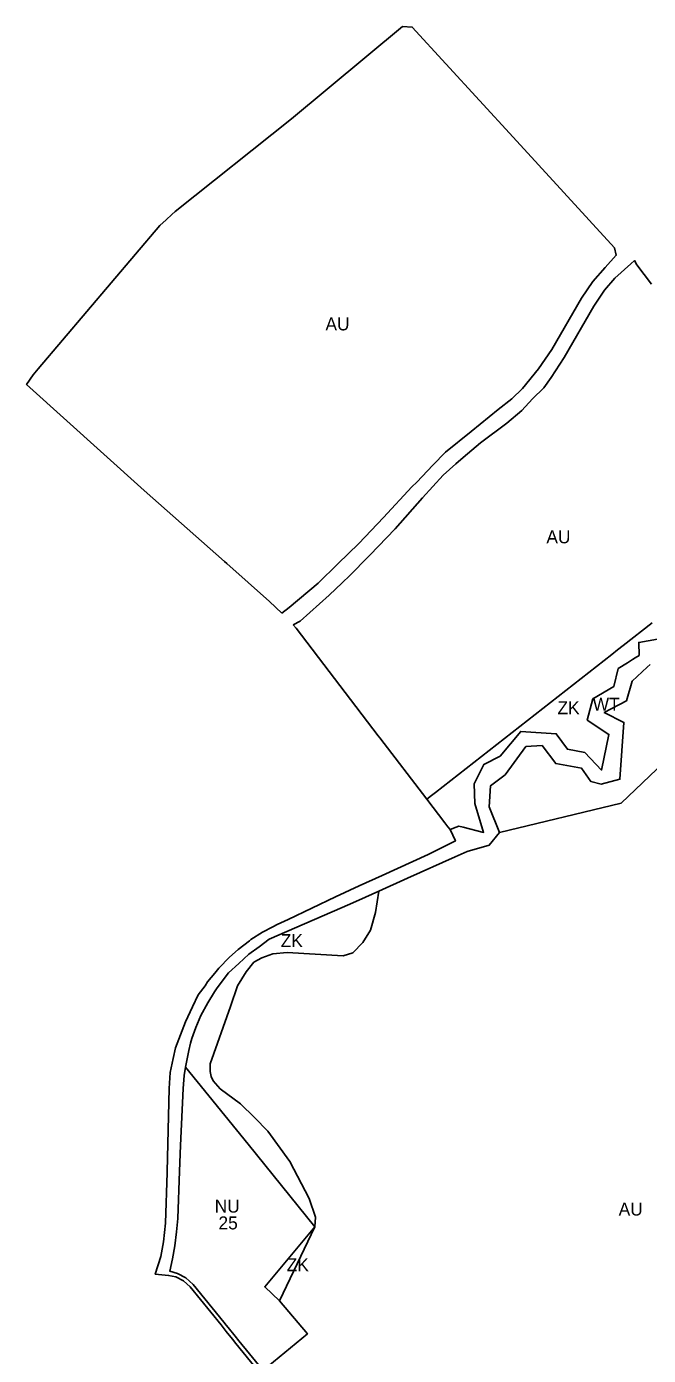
# Model space of a CAD drawing. Extents: x -522079 to -518833, y -1142398 to -1139961.
# Drawn here: x -522079 to -521599, y -1141061 to -1140036 of the extents above; entities that cross this region are included whole.
import ezdxf

# ---------------------------------------------------------------- set-up
doc = ezdxf.new("R2010")
doc.units = 0
for name, color, linetype in [('90640013', 7, 'Continuous'), ('90710013', 7, 'Continuous'), ('90730023', 7, 'Continuous'), ('90750013', 7, 'Continuous'), ('ID_navrh', 7, 'Continuous')]:
    doc.layers.add(name, color=color, linetype=linetype)

msp = doc.modelspace()

# ---------------------------------------------------------------- linework, layer by layer
at = {"layer": '90640013'}
for points in [[(-521592.51, -1140508.64), (-521606.9, -1140511.13), (-521606.6, -1140521.1), (-521609.78, -1140523.1), (-521611.69, -1140524.3), (-521615.57, -1140526.74), (-521622.75, -1140531.26), (-521626.2, -1140545.21), (-521642.26, -1140554.66), (-521646.65, -1140571), (-521629.87, -1140582.04), (-521635.54, -1140609.6), (-521648.43, -1140596.09), (-521661.89, -1140593.5), (-521670.5, -1140581.53), (-521698, -1140579.74), (-521713.89, -1140598.84), (-521726.52, -1140605.2), (-521734.01, -1140620.28), (-521733.38, -1140635.33), (-521726.67, -1140657.74), (-521742.5, -1140653.65), (-521745.77, -1140652.8), (-521747.72, -1140653.54), (-521752.49, -1140655.36), (-521748.38, -1140664.24), (-521769.34, -1140674.65), (-521804.78, -1140690.88), (-521822.52, -1140699.01), (-521840.82, -1140707.39), (-521877.29, -1140724.81), (-521885.86, -1140728.85), (-521889.34, -1140730.49), (-521897.11, -1140734.61), (-521906.16, -1140740.38), (-521907.36, -1140741.3), (-521915.99, -1140747.92), (-521922.69, -1140753.87), (-521930.99, -1140762.54), (-521933.99, -1140766.2), (-521939.58, -1140773.02), (-521941.53, -1140776.07), (-521946.81, -1140782.96), (-521951.34, -1140792.2), (-521956.64, -1140803.89), (-521960.5, -1140813.97), (-521964.35, -1140823.92), (-521966.23, -1140832.06), (-521968.4, -1140842.82), (-521969.35, -1140855.23), (-521970.78, -1140919.37), (-521970.73, -1140920.13), (-521972.01, -1140959.19), (-521973.56, -1140973.69), (-521975.77, -1140984.83), (-521980.02, -1140998.54), (-521969.71, -1140999.55), (-521964.16, -1141000.63), (-521958.05, -1141003.66), (-521952.92, -1141008.37), (-521929.14, -1141037.67), (-521925.3, -1141042.86), (-521920.31, -1141048.71), (-521917.71, -1141051.91), (-521886.17, -1141090.77)], [(-521896.82, -1141072.9), (-521915.45, -1141049.99), (-521918.24, -1141046.46), (-521923.77, -1141039.61), (-521925.13, -1141037.95), (-521927.04, -1141035.61), (-521950.59, -1141006.47), (-521956.25, -1141001.25), (-521962.85, -1140997.93), (-521968.74, -1140996.16), (-521966.75, -1140986.81), (-521964.79, -1140976.78), (-521963.61, -1140965.78), (-521962.64, -1140955.52), (-521961.27, -1140919.13), (-521960.41, -1140899.15), (-521958.48, -1140855.25), (-521957.55, -1140845.37), (-521956.51, -1140838.94), (-521956.06, -1140836.18), (-521953.99, -1140825.94), (-521952.78, -1140820.25), (-521951.85, -1140816.81), (-521948.6, -1140808.27), (-521944.68, -1140798.86), (-521939.28, -1140789.17), (-521934.35, -1140780.63), (-521932.78, -1140778.46), (-521929.14, -1140773.45), (-521923.36, -1140766.09), (-521915.35, -1140758.73), (-521907.65, -1140751.59), (-521899.73, -1140746), (-521892.09, -1140739.95), (-521829.78, -1140713), (-521817.76, -1140707.64), (-521807.36, -1140702.96), (-521785.36, -1140693.05), (-521748.53, -1140676.5), (-521739.27, -1140672.34), (-521722.24, -1140667.6), (-521714.47, -1140657.84), (-521722.39, -1140637.91), (-521721.28, -1140621.72), (-521710.1, -1140613.29), (-521693.94, -1140591.41), (-521681.44, -1140590.68), (-521670.89, -1140604.59), (-521650.96, -1140608.19), (-521643.99, -1140618.34), (-521635.78, -1140620.38), (-521621.47, -1140616.67), (-521618.3, -1140572.85), (-521633.5, -1140565.29), (-521616.47, -1140556.14), (-521611.96, -1140540.86), (-521600.31, -1140530.11), (-521598.04, -1140528.01)]]:
    msp.add_lwpolyline(points, dxfattribs=at)
at = {"layer": '90710013'}
for points in [[(-521596.59, -1140495.96), (-521619, -1140513.52), (-521623.29, -1140516.88), (-521627.73, -1140520.35), (-521763.73, -1140626.86), (-521766.84, -1140629.25), (-521770.53, -1140631.96)], [(-521770.53, -1140631.96), (-521756.45, -1140650.36), (-521754.23, -1140653.26), (-521752.49, -1140655.36), (-521747.72, -1140653.54), (-521745.77, -1140652.8), (-521742.5, -1140653.65), (-521726.67, -1140657.74), (-521733.38, -1140635.33), (-521734.01, -1140620.28), (-521726.52, -1140605.2), (-521713.89, -1140598.84), (-521698, -1140579.74), (-521670.5, -1140581.53), (-521661.89, -1140593.5), (-521648.43, -1140596.09), (-521635.54, -1140609.6), (-521629.87, -1140582.04), (-521646.65, -1140571), (-521642.26, -1140554.66), (-521626.2, -1140545.21), (-521622.75, -1140531.26), (-521615.57, -1140526.74), (-521611.69, -1140524.3), (-521609.78, -1140523.1), (-521606.6, -1140521.1), (-521606.9, -1140511.13), (-521592.51, -1140508.64)], [(-521598.04, -1140528.01), (-521600.31, -1140530.11), (-521611.96, -1140540.86), (-521616.47, -1140556.14), (-521633.5, -1140565.29), (-521618.3, -1140572.85), (-521621.47, -1140616.67), (-521635.78, -1140620.38), (-521643.99, -1140618.34), (-521650.96, -1140608.19), (-521670.89, -1140604.59), (-521681.44, -1140590.68), (-521693.94, -1140591.41), (-521710.1, -1140613.29), (-521721.28, -1140621.72), (-521722.39, -1140637.91), (-521714.47, -1140657.84), (-521620.49, -1140635.2), (-521571.05, -1140588.16)], [(-521956.51, -1140838.94), (-521908.14, -1140898.33), (-521856.78, -1140962.03), (-521856.34, -1140954.66), (-521861.19, -1140940.1), (-521876.05, -1140911.7), (-521892.98, -1140888.32), (-521903.5, -1140877.67), (-521914.17, -1140867.15), (-521929.85, -1140855.48), (-521935.25, -1140849.47), (-521936.78, -1140845.99), (-521937.7, -1140842.11), (-521937.7, -1140836.22), (-521922.02, -1140791.92), (-521916.45, -1140776.17), (-521909.81, -1140765.14), (-521903.79, -1140757.88), (-521897.69, -1140754.5), (-521889.21, -1140751.5), (-521878.09, -1140750.44), (-521834.89, -1140752.79), (-521827.42, -1140750.62), (-521819.79, -1140742.52), (-521813.81, -1140733.11), (-521809.93, -1140719.56), (-521807.36, -1140702.96), (-521817.76, -1140707.64), (-521829.78, -1140713), (-521892.09, -1140739.95), (-521899.73, -1140746), (-521907.65, -1140751.59), (-521915.35, -1140758.73), (-521923.36, -1140766.09), (-521929.14, -1140773.45), (-521932.78, -1140778.46), (-521934.35, -1140780.63), (-521939.28, -1140789.17), (-521944.68, -1140798.86), (-521948.6, -1140808.27), (-521951.85, -1140816.81), (-521952.78, -1140820.25), (-521953.99, -1140825.94), (-521956.06, -1140836.18), (-521956.51, -1140838.94)]]:
    msp.add_lwpolyline(points, dxfattribs=at)
msp.add_lwpolyline([(-521884.07, -1141019.15), (-521856.78, -1140962.03), (-521895.5, -1141008.4)], close=True, dxfattribs=at)
at = {"layer": '90730023'}
msp.add_lwpolyline([(-521893.06, -1141069.8), (-521862.5, -1141044.56), (-521884.07, -1141019.15), (-521895.5, -1141008.4), (-521856.78, -1140962.03), (-521908.14, -1140898.33), (-521956.51, -1140838.94), (-521957.55, -1140845.37), (-521958.48, -1140855.25), (-521960.41, -1140899.15), (-521961.27, -1140919.13), (-521962.64, -1140955.52), (-521963.61, -1140965.78), (-521964.79, -1140976.78), (-521966.75, -1140986.81), (-521968.74, -1140996.16), (-521962.85, -1140997.93), (-521956.25, -1141001.25), (-521950.59, -1141006.47), (-521927.04, -1141035.61), (-521925.13, -1141037.95), (-521923.77, -1141039.61), (-521918.24, -1141046.46), (-521915.45, -1141049.99), (-521896.82, -1141072.9)], dxfattribs=at)
at = {"layer": '90750013'}
msp.add_lwpolyline([(-521882.18, -1140488.56), (-521876.66, -1140484.09), (-521854.3, -1140465.27), (-521839, -1140450.48), (-521822.79, -1140434.86), (-521803.88, -1140414.74), (-521781.95, -1140390.97), (-521778.1, -1140387.34), (-521765.79, -1140374.26), (-521755.99, -1140364.38), (-521736.25, -1140348.4), (-521715.5, -1140331.4), (-521704.79, -1140323.18), (-521696.71, -1140315.1), (-521684.15, -1140299.89), (-521673.96, -1140285.19), (-521651.12, -1140245.38), (-521642.31, -1140232.52), (-521632.85, -1140221.77), (-521624.31, -1140212.38), (-521625.65, -1140206.61), (-521703.78, -1140121.15), (-521781.62, -1140036.36), (-521789.25, -1140035.92), (-521874.73, -1140107.13), (-521964.54, -1140178.59), (-521967.11, -1140180.95), (-521971.46, -1140184.95), (-521976.31, -1140189.41), (-522070.23, -1140300.06), (-522074.19, -1140304.73), (-522079.24, -1140312.2), (-521988.52, -1140393.86), (-521926.43, -1140448.75), (-521924.65, -1140450.32), (-521891.73, -1140479.43)], close=True, dxfattribs=at)
for points in [[(-521596.95, -1140234.61), (-521608.33, -1140219.87), (-521610.22, -1140216.5), (-521613.09, -1140218.9), (-521625.36, -1140230.13), (-521633.25, -1140239.25), (-521641.46, -1140251.62), (-521664.44, -1140291.34), (-521674.58, -1140306.67), (-521680.22, -1140314.66), (-521688.85, -1140323.27), (-521697.12, -1140332.11), (-521708.67, -1140341.98), (-521728.93, -1140357.06), (-521742.3, -1140368.5), (-521747.91, -1140373.33), (-521757.78, -1140381.98), (-521773.82, -1140399.6), (-521794.87, -1140423.48), (-521814.39, -1140443.83), (-521815.4, -1140444.86), (-521829.77, -1140459.58), (-521835.62, -1140465.09), (-521845.84, -1140474.71), (-521868.24, -1140494.75), (-521873.47, -1140497.6)], [(-521873.47, -1140497.6), (-521871.3, -1140500.06), (-521807.95, -1140583.04), (-521806.71, -1140584.66), (-521770.53, -1140631.96), (-521766.84, -1140629.25), (-521763.73, -1140626.86), (-521627.73, -1140520.35), (-521623.29, -1140516.88), (-521619, -1140513.52), (-521596.59, -1140495.96)], [(-521571.05, -1140588.16), (-521620.49, -1140635.2), (-521714.47, -1140657.84), (-521722.24, -1140667.6), (-521739.27, -1140672.34), (-521748.53, -1140676.5), (-521785.36, -1140693.05), (-521807.36, -1140702.96), (-521809.93, -1140719.56), (-521813.81, -1140733.11), (-521819.79, -1140742.52), (-521827.42, -1140750.62), (-521834.89, -1140752.79), (-521878.09, -1140750.44), (-521889.21, -1140751.5), (-521897.69, -1140754.5), (-521903.79, -1140757.88), (-521909.81, -1140765.14), (-521916.45, -1140776.17), (-521922.02, -1140791.92), (-521937.7, -1140836.22), (-521937.7, -1140842.11), (-521936.78, -1140845.99), (-521935.25, -1140849.47), (-521929.85, -1140855.48), (-521914.17, -1140867.15), (-521903.5, -1140877.67), (-521892.98, -1140888.32), (-521876.05, -1140911.7), (-521861.19, -1140940.1), (-521856.34, -1140954.66), (-521856.78, -1140962.03), (-521884.07, -1141019.15), (-521862.5, -1141044.56), (-521893.06, -1141069.8)]]:
    msp.add_lwpolyline(points, dxfattribs=at)

# ---------------------------------------------------------------- texts
at = {"layer": '90640013'}
msp.add_text('WT', height=10, rotation=360, dxfattribs=at).set_placement((-521642.43, -1140563.78))
at = {"layer": '90710013'}
for rotation, p in [(360, (-521669.61, -1140566.51)), (0, (-521883.13, -1140746.17)), (0, (-521878.57, -1140996.26))]:
    msp.add_text('ZK', height=10, rotation=rotation, dxfattribs=at).set_placement(p)
at = {"layer": '90730023'}
msp.add_text('NU', height=10, rotation=0, dxfattribs=at).set_placement((-521934.08, -1140951.06))
at = {"layer": '90750013'}
for rotation, p in [(0, (-521848.63, -1140270.35)), (360, (-521678.17, -1140434.63)), (360, (-521622.39, -1140953.32))]:
    msp.add_text('AU', height=10, rotation=rotation, dxfattribs=at).set_placement(p)
at = {"layer": 'ID_navrh'}
msp.add_text('25', height=10, rotation=360, dxfattribs=at).set_placement((-521931.17, -1140964))

doc.saveas('drawing.dxf')
